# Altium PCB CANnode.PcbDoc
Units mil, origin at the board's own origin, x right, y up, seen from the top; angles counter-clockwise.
Board outline 2780 x 2140 mil, 4 copper layers (Top Layer, GND, 3V3, Bottom Layer), stack 53.911 mil thick; 99 components, 91 nets, 421 pads, 118 vias.
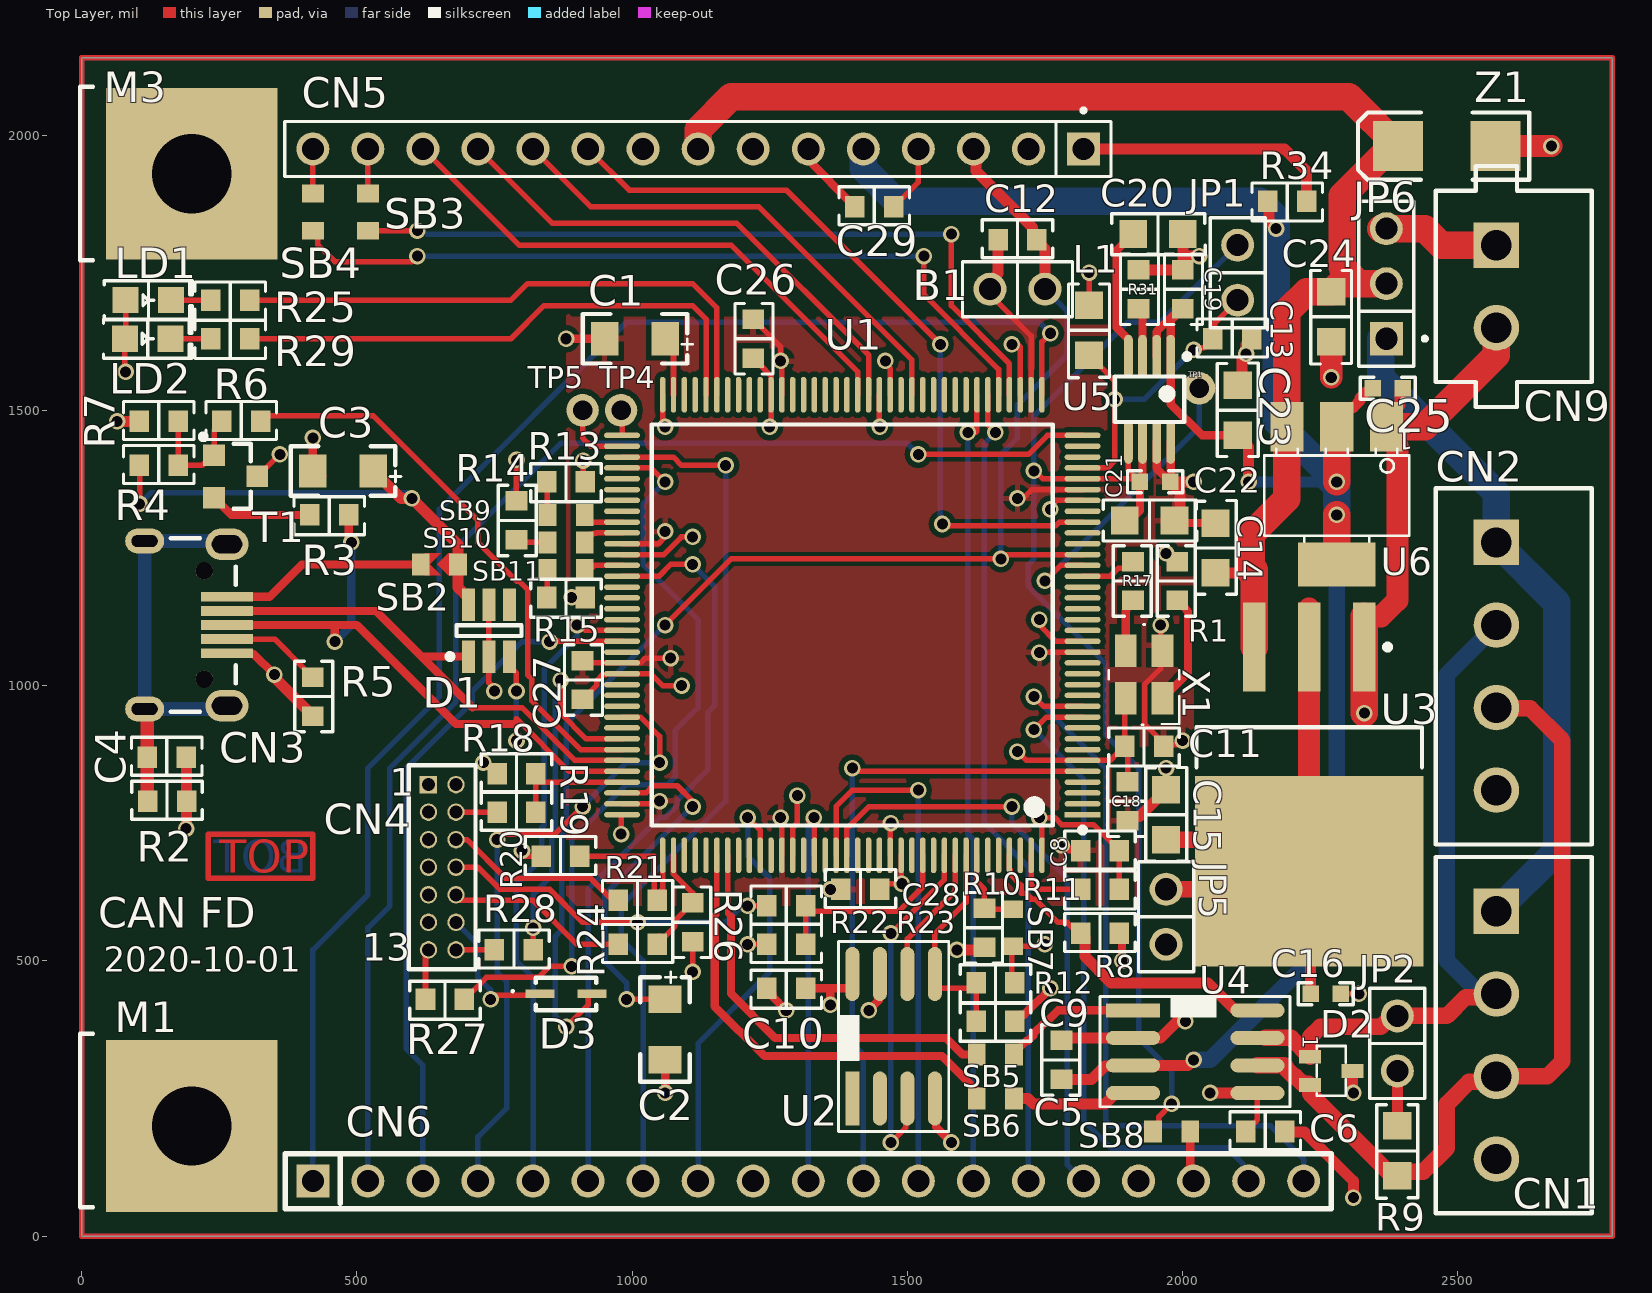
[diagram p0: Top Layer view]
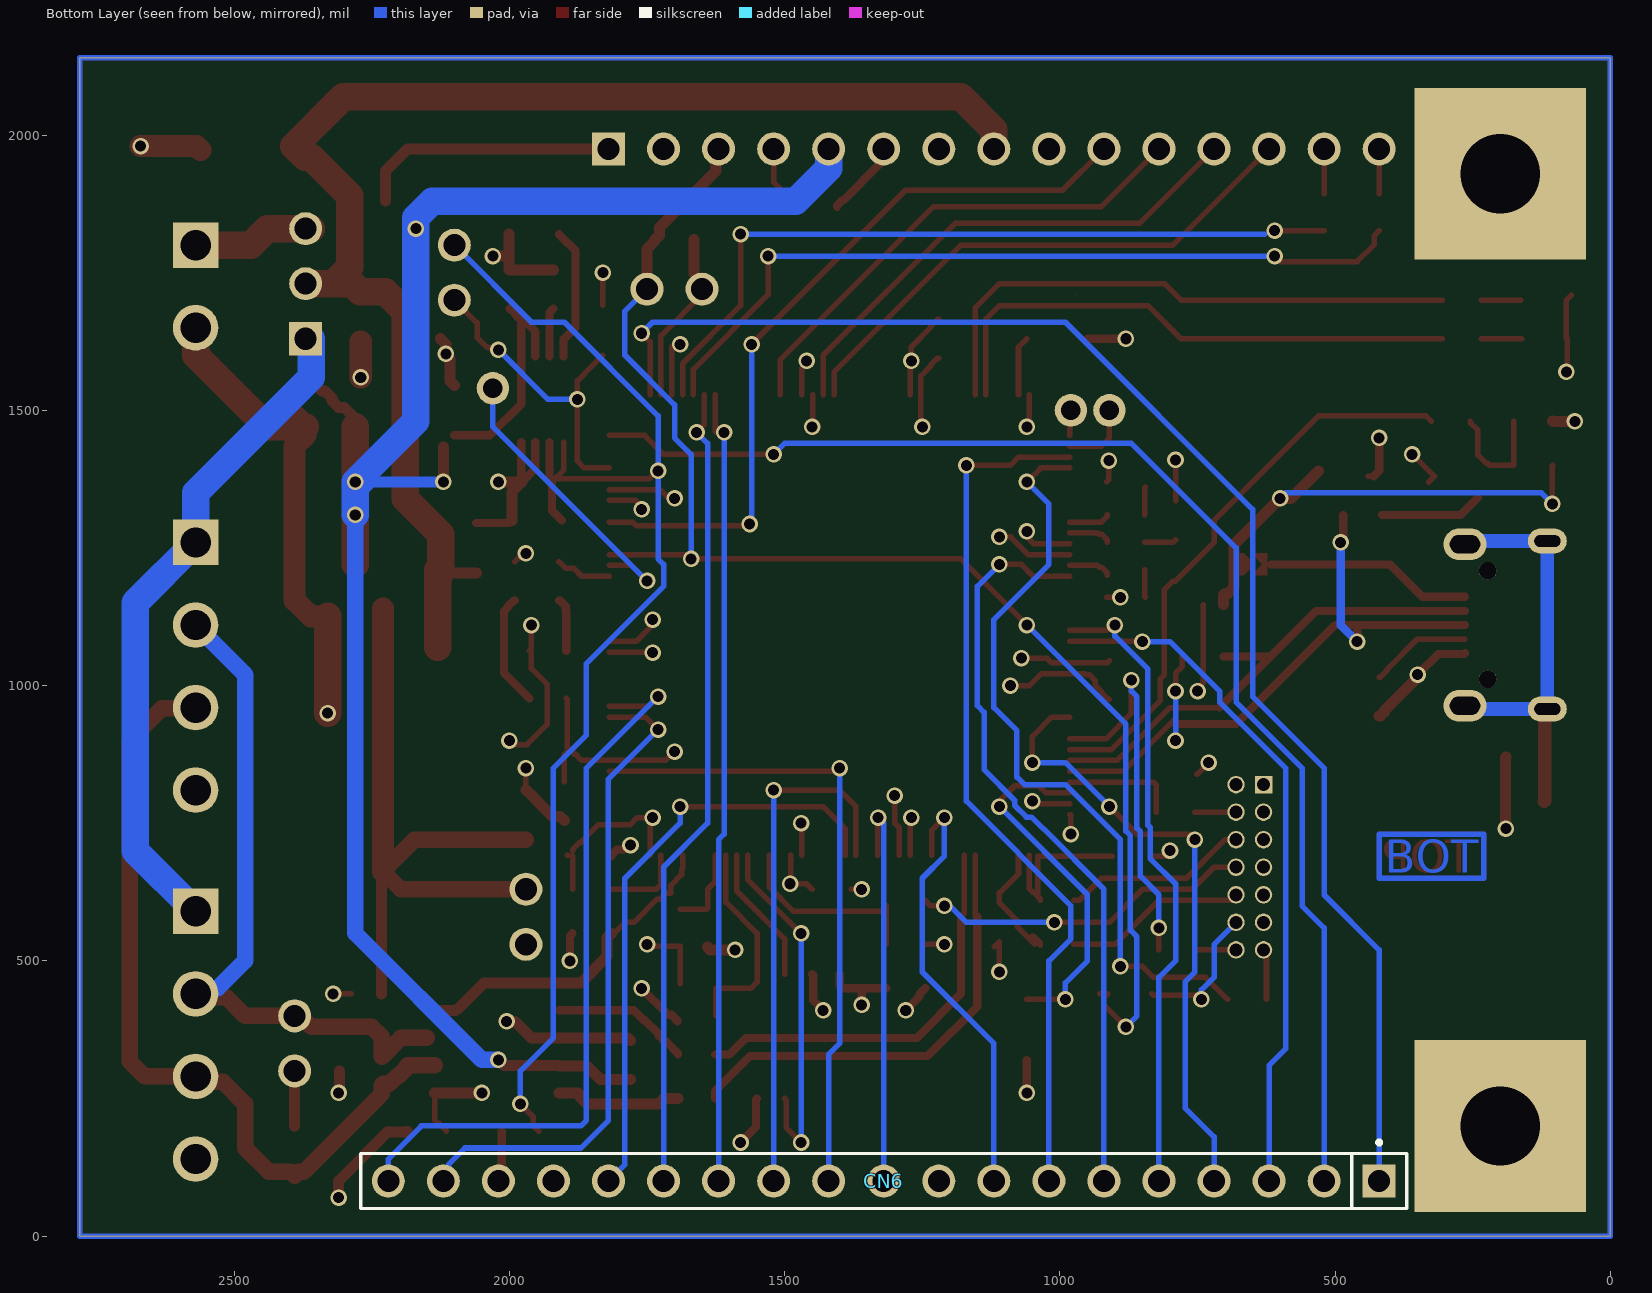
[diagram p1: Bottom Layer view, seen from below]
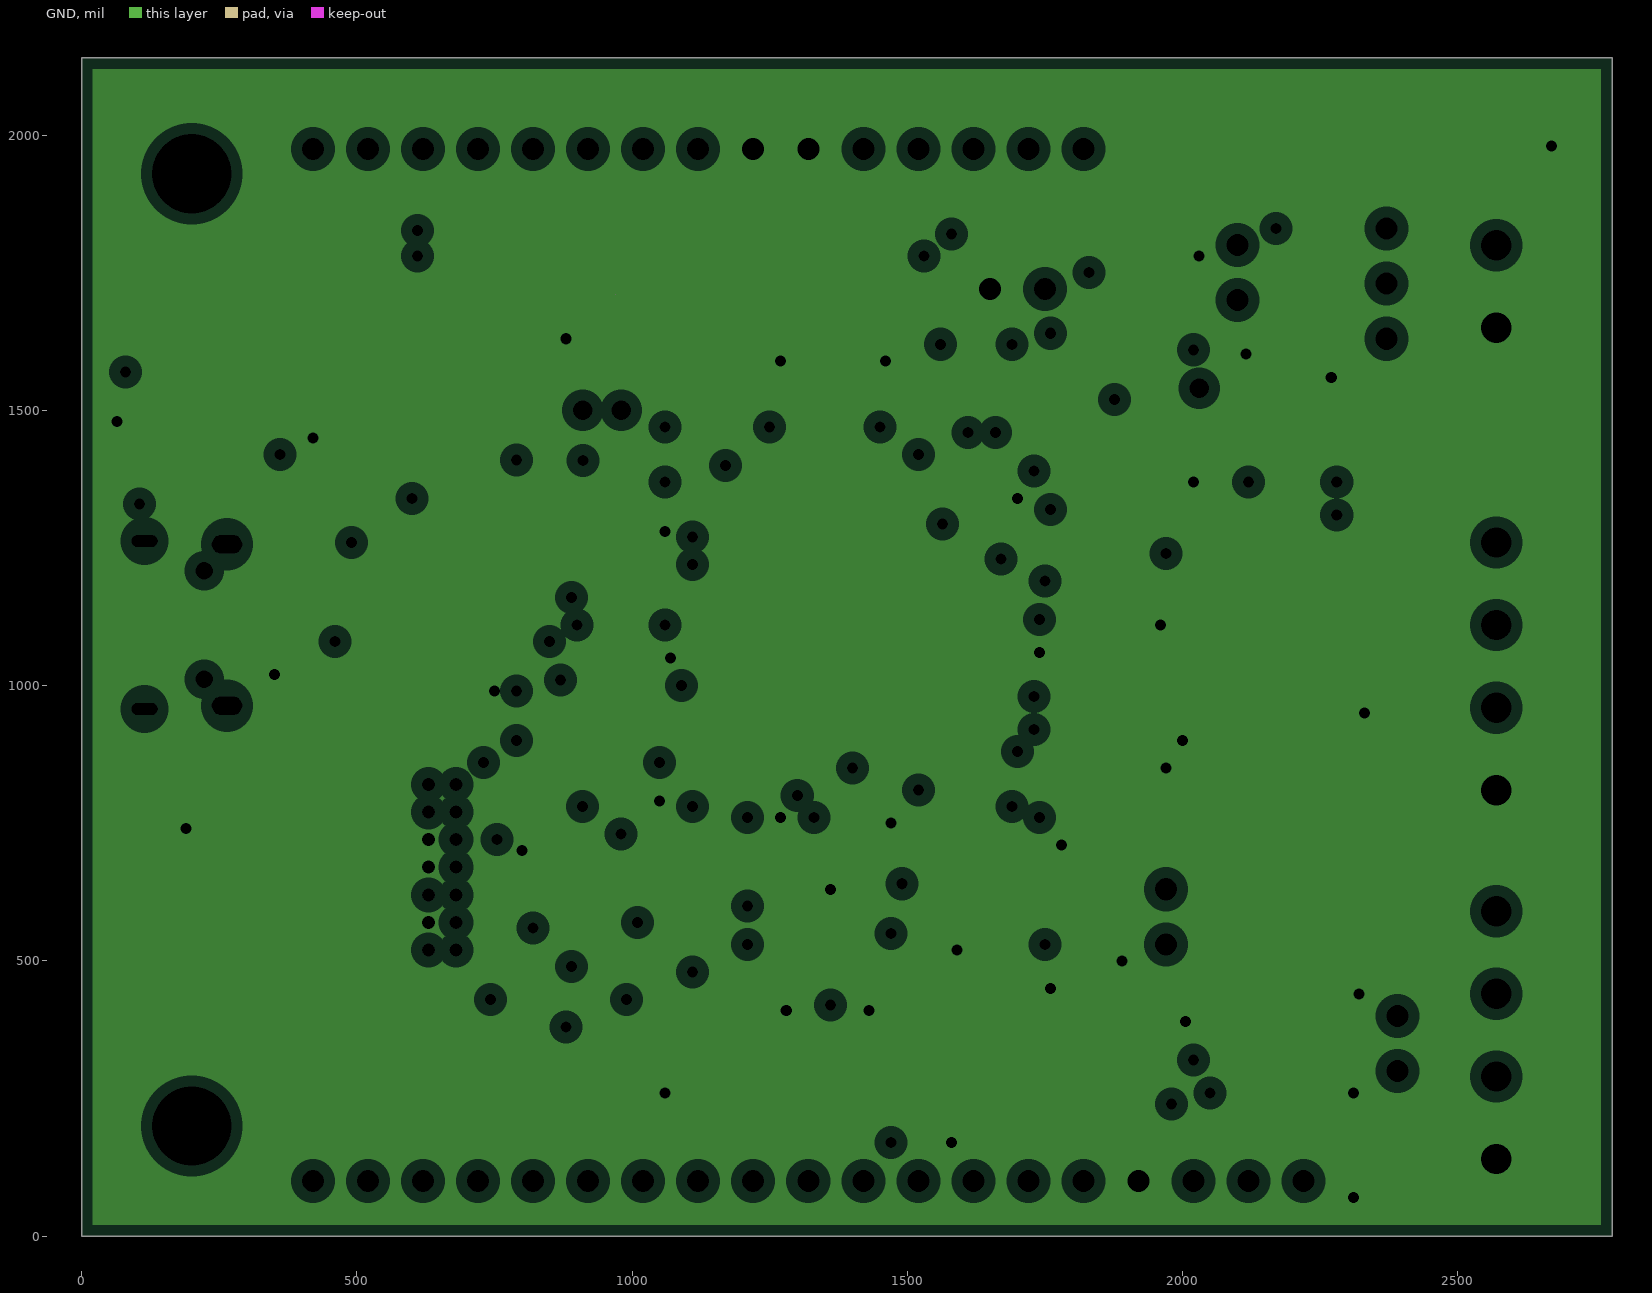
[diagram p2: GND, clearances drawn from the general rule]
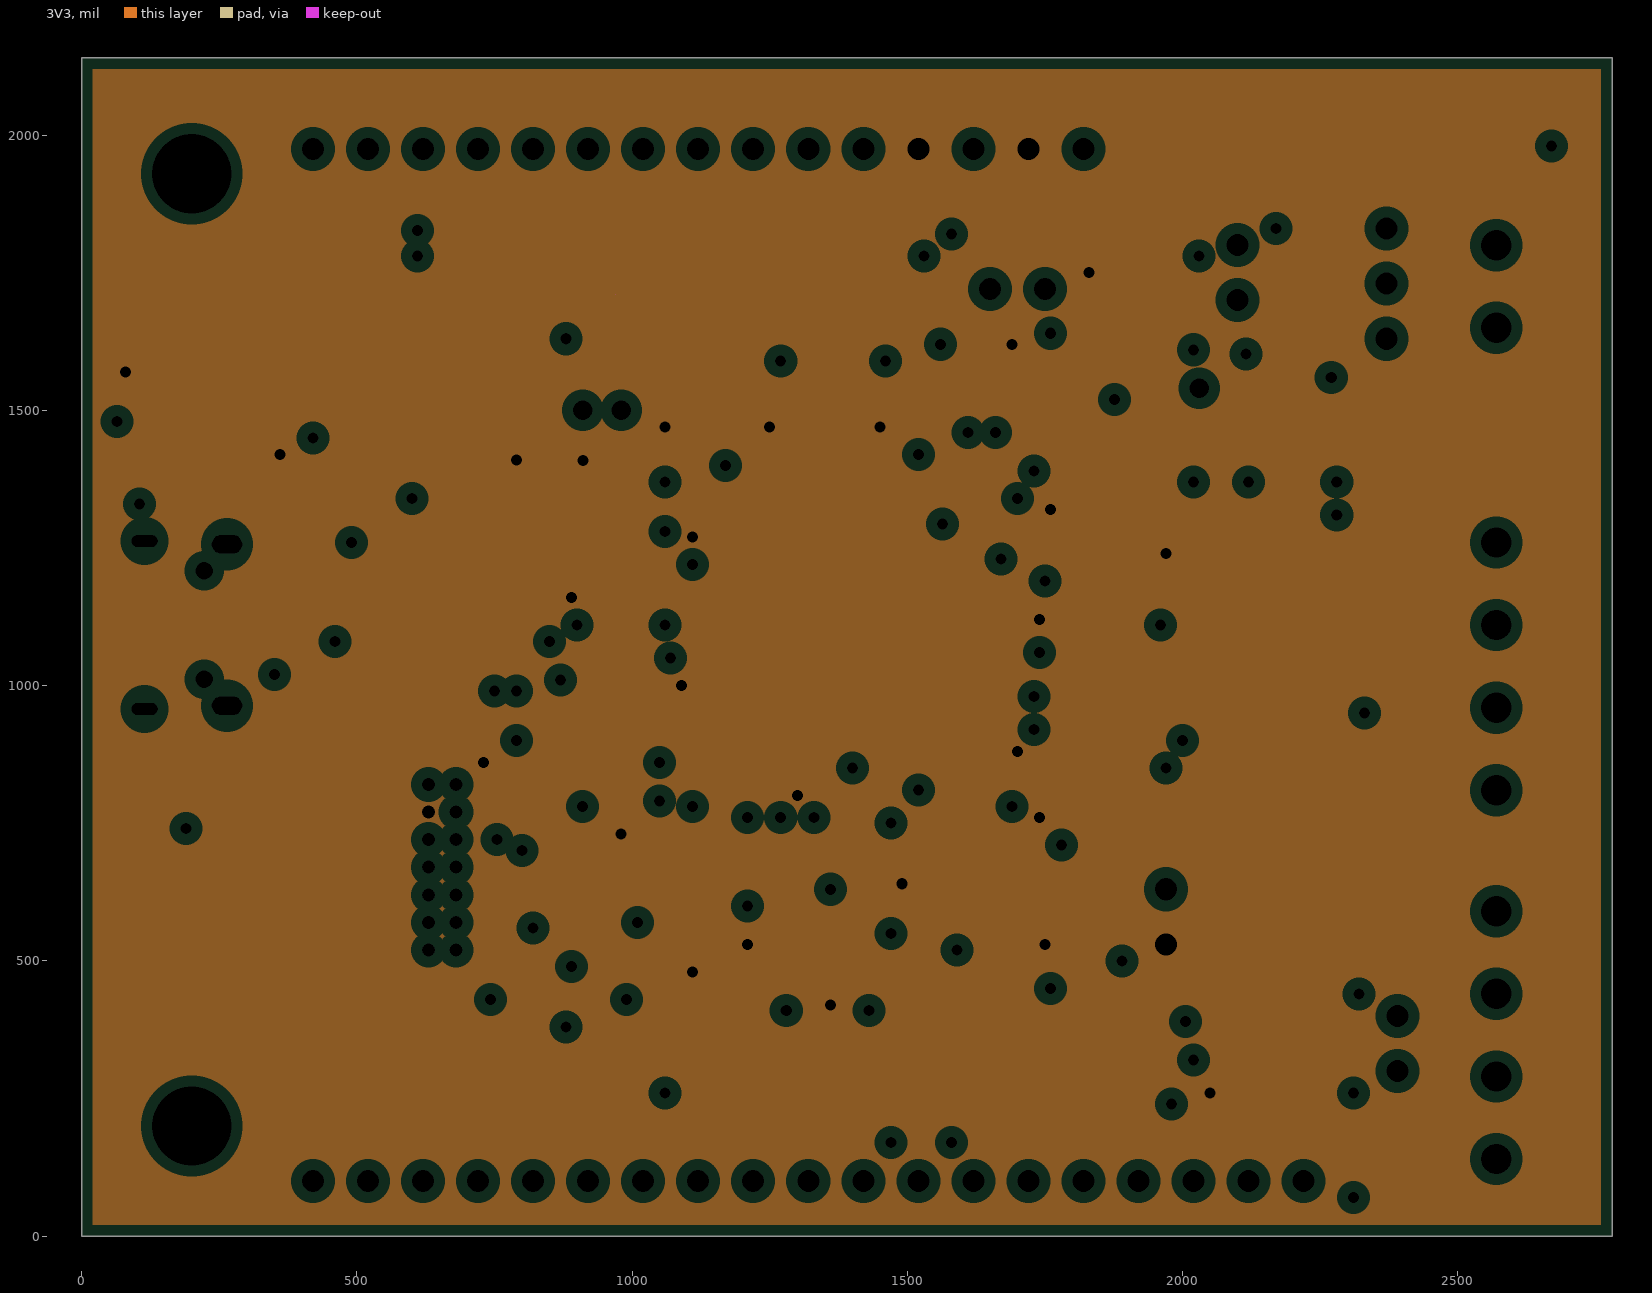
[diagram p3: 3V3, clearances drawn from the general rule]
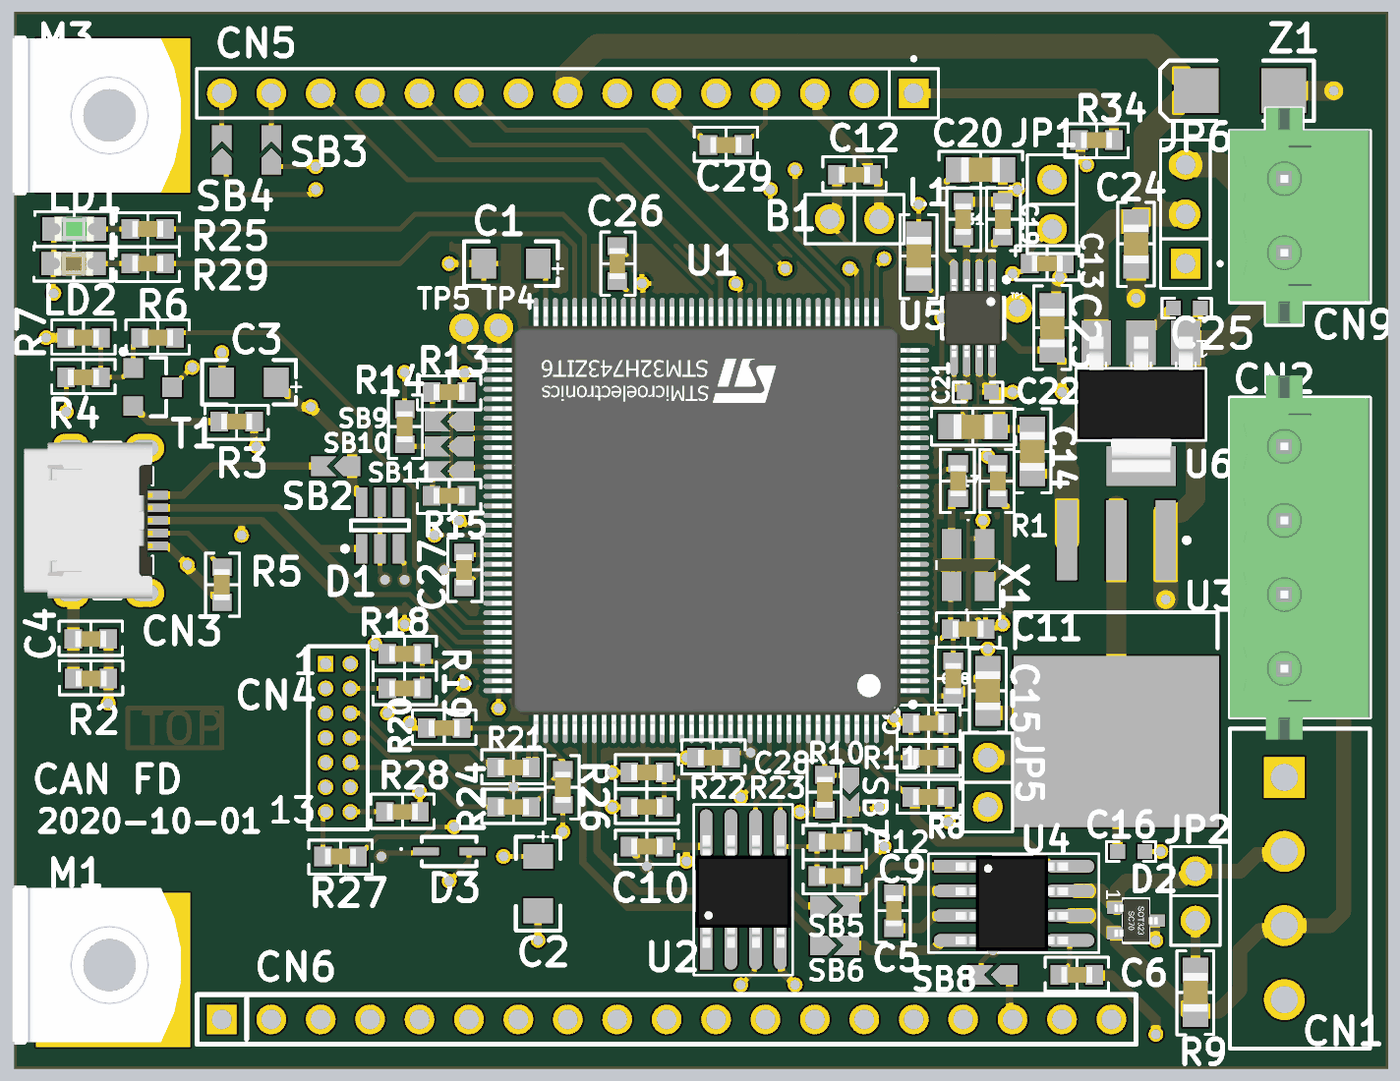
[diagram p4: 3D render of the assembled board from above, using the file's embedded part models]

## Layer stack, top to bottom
Top Solder: solder mask 1, SM-001, Dk 4
Top Layer: signal copper 1.3778
Dielectric 1: prepreg 5.1, PP-017, Dk 4.3
Dielectric 2: prepreg 5.1, PP-017, Dk 4.3
GND: plane copper 1.3778, net GND
Dielectric 3: core 28, Core-039, Dk 4.8
3V3: plane copper 1.3778, net 3V3
Dielectric 4: prepreg 5.1, PP-017, Dk 4.3
Dielectric 5: prepreg 5.1, PP-017, Dk 4.3
Bottom Layer: signal copper 1.3778
Bottom Solder: solder mask 1, SM-001, Dk 4

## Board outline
2780,0 2780,2140 0,2140 0,0
cut-out: 970,1710

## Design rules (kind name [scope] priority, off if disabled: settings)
Clearance [All] p1: gap=10 ignorepadtopadclearanceinfootprint=FALSE except(0: SMDPad-Region; 7: SMDPad-SMDPad; 8: Track-Track Track-SMDPad Track-THPad Track-Via Track-Fill Track-Poly Track-Region Track-Text Track-Hole SMDPad-THPad THPad-THPad Region-Region Region-Text Region-Hole)
ComponentClearance [All] p1: gap=0 collisioncheckmode=3 verticalgap=0 showdistances=FALSE
HoleSize [All] p1: absolutevalues=TRUE maxlimit=150 minlimit=15 maxpercent=80.000 minpercent=20.000
MinimumSolderMaskSliver [All] p1: minsoldermaskwidth=4
PlaneClearance [All] p1: clearance=20
PlaneConnect PlanePwr [InNetClass('3V3')] p1: pad.planeconnectstyle=Relief pad.reliefexpansion=10 pad.reliefentries=4 pad.reliefconductorwidth=15 pad.reliefairgap=15 via.planeconnectstyle=Direct via.reliefexpansion=10 via.reliefentries=4 via.reliefconductorwidth=10 via.reliefairgap=15
PlaneConnect PlaneGND [InNetClass('GND')] p2: pad.planeconnectstyle=Relief pad.reliefexpansion=10 pad.reliefentries=4 pad.reliefconductorwidth=15 pad.reliefairgap=15 via.planeconnectstyle=Direct via.reliefexpansion=20 via.reliefentries=4 via.reliefconductorwidth=15 via.reliefairgap=15
PolygonConnect [All] p1: connectstyle=Relief reliefconductorwidth=10 reliefentries=4 polygonreliefangle="90 Angle" airgapwidth=10
RoutingVias RoutingVias_1 [All] p1 off: holewidth=28 width=50 viastyle="Through Hole" minholewidth=28 minwidth=50 maxholewidth=28 maxwidth=50
RoutingVias [All] p2: holewidth=20 width=30 viastyle="Through Hole" minholewidth=20 minwidth=30 maxholewidth=20 maxwidth=30
SilkToSilkClearance [All] p1: silktosilkclearance=0
SilkToSolderMaskClearance [IsPad] p1: minsilkscreentomaskgap=0 clearancetoexposedcopper=TRUE
SolderMaskExpansion [All] p1: expansion=4
Width [All] p1: maxlimit=50 minlimit=10 preferedwidth=15 minimp=50.000000 maximp=50.000000 favimp=50.000000
23 further rules are at their usual default settings.

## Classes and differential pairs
net class 3V3: 3V3
net class GND: GND
component class U_Arduino: CN5 CN6 R34 SB3 SB4 SB8
component class U_PWR: C1 C2 C13 C14 C15 C16 C18 C19 C20 C21 C22 C23 C24 C25 CN9 JP1 JP5 JP6 L1 R31 U1 U3 U5 U6 Z1
component class U_MCU: B1 C8 C9 C10 C11 C12 C26 C27 C28 C29 CN4 D3 LD1 LD2 R1 R10 R11 R12 R13 R14 R15 R17 R18 R19 R20 R21 R22 R23 R24 R25 R26 R27 R28 R29 SB5 SB6 SB7 SB9 SB10 SB11 TP1 TP4 TP5 U2 X1
component class U_CANUSB: C3 C4 C5 C6 CN1 CN2 CN3 D1 D2 JP2 R2 R3 R4 R5 R6 R7 R8 R9 SB2 T1 U4
component class TopView: M1 M3

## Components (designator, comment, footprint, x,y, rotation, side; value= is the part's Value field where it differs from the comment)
B1 "" SIP2/2.54 1650,1720 r0 top
C1 "2.2uF" TAN-A 1060,1630 r0 top
C2 "2.2uF" TAN-A 1060,430 r90 top
C3 "4.7uF" TAN-A 530,1390 r0 top value=4.7µF
C4 "100nF" 0603#1 154.7,870 r0 top
C5 "100nF" 0603#1 1780,320 r90 top
C6 "100nF" 0603#1 2150,190 r0 top
C8 "Capacitor" 0603#1 1850,700 r0 top value=100nF
C9 "Capacitor" 0603#1 1660,390 r180 top value=30pF
C10 "Capacitor" 0603#1 1280,450 r180 top value=100nF
C11 "Capacitor" 0603#1 1930,890 r180 top value=100nF
C12 "100nF" 0603#1 1700,1810 r0 top value=100pF
C13 "Capacitor" 0603#1 2090,1630 r0 top value=100nF
C14 "10uF/25V" 0805 2060,1250 r90 top value=10uF
C15 "10uF/25V" 0805 1970,765.28 r90 top value=10uF
C16 "100nF" 0603C 2260,440 r180 top value=10nF
C18 "Capacitor" 0603#1 1900,790 r90 top value=100nF
C19 "100nF" 0603#1 2000,1720 r270 top value=10nF
C20 "1uF" 0805 1955.28,1820 r0 top
C21 "47uF" 0805 1940,1300 r0 top value=1uF
C22 "100nF" 0603C 1950,1370 r180 top value=10nF
C23 "10uF/25V" 0805 2100,1500 r90 top value=10uF
C24 "10uF/25V" 0805 2270,1670 r270 top value=10uF
C25 "100nF" 0603C 2372.5,1540 r180 top value=10nF
C26 "Capacitor" 0603#1 1220,1630 r270 top value=100nF
C27 "Capacitor" 0603#1 910,1010 r270 top value=100nF
C28 "Capacitor" 0603#2 1414.7,630 r0 top value=100nF
C29 "Capacitor" 0603#1 1440,1870 r0 top value=100nF
CN1 "MC000130" 691305330004 2601.5,365 r270 top
CN2 "MC000130" 691305330004 2601.5,1035 r270 top
CN3 "629105150521" USB_micro_629105150521 150,1110 r270 top
CN4 "STLINK_V3SET" HDR2X7--50mil 630,820 r270 top
CN5 "SSW-115-01-T-S" SIP15 1820,1974.8 r180 top
CN6 "SSW-119-01-T-S" sip19 420,100 r0 bottom
CN9 "691321300002" 691305330002 2601.5,1725 r270 top
D1 "ESDA6V1BC6" SOT23-6-L 740,1100 r90 top
D2 "ESDCAN02-2BWY" DIO_SOT323 2270,300 r270 top
D3 "BAT60JFILM" SOD-323 880,440 r180 top
JP1 "" SIP2/2.54 2100,1800 r270 top
JP2 "" SIP2/2.54 2390,400 r270 top
JP5 "" SIP2/2.54 1970,530 r90 top
JP6 "" SIP3 2370,1630 r90 top
L1 "BEAD" 0805 1830,1645.28 r270 top value=0.27@250MHz
LD1 "LED_green" "LED 0805/2012 GREEN" 121.34,1700 r0 top value=Green,KP-2012LSGC
LD2 "LED_red" "LED 0805/2012 RED" 120,1630 r0 top value=Red,KPT-2012EC
M1 "" "Keystone 614"#1 190,210 r0 top
M3 "" "Keystone 614"#2 190,1930 r0 top
R1 "Resistor" 0603#1 1990,1190 r90 top value=4K7
R2 "330" 0603#1 155.3,790 r0 top
R3 "1K5" 0603#1 450,1310 r180 top
R4 "10K" 0603#1 140,1400 r0 top
R5 "100K" 0603#1 420,980 r270 top
R6 "100" 0603#1 290,1480 r0 top
R7 "36K" 0603#1 140,1480 r0 top
R8 "10K" 0603#1 1850,550 r0 top
R9 "120" 0805 2390,154.72 r270 top
R10 "Resistor" 0603#1 1640,560 r90 top value=100K
R11 "Resistor" 0603#1 1850,630 r180 top value=10K
R12 "Resistor" 0603#1 1660,460 r180 top value=4K7
R13 "Resistor" 0603#1 880,1370 r180 top value=100K
R14 "Resistor" 0603#1 790,1300 r270 top value=100K
R15 "Resistor" 0603#3 880,1160 r180 top value=100K
R17 "Resistor" 0603#1 1910,1190 r90 top value=51R
R18 "Resistor" 0603#1 790,840 r0 top value=10K
R19 "22" 0603#1 790,770 r0 top
R20 "Resistor" 0603#1 870,690 r0 top value=10K
R21 "22" 0603#3 1010,610 r0 top
R22 "22" 0603#1 1280,600 r0 top
R23 "Resistor" 0603#1 1280,530 r0 top value=10K
R24 "22" 0603#3 1010,530 r0 top
R25 "Resistor" 0603#1 270,1700 r180 top value=1K
R26 "Resistor" 0603#1 1110,570 r90 top value=10K
R27 "22" 0603#1 660,430 r180 top
R28 "22" 0603#1 785.3,520 r0 top
R29 "Resistor" 0603#1 270,1630 r180 top value=1K
R31 "120K" 0603#1 1920,1720 r270 top
R34 "Resistor" 0603#1 2190,1880 r180 top value=1K
SB2 "Open" SB0603#1 650,1220 r0 top
SB3 "SB_ON" SB0603#2 520,1860 r270 top
SB4 "SB_ON" SB0603#2 420,1860 r270 top
SB5 "SB_ON" SB0603#2 1660,330 r180 top
SB6 "SB_ON" SB0603#2 1660,250 r180 top
SB7 "SB_ON" SB0603#3 1690,560 r90 top
SB8 "SB_OFF" SB0603#2 1980,190 r0 top
SB9 "SB_OFF" SB0603#3 880,1310 r0 top
SB10 "SB_OFF" SB0603#3 880,1260 r0 top
SB11 "SB_OFF" SB0603#3 880,1210 r0 top
T1 "BC847A" SOT-23 280,1380 r270 top
TP1 "OSCO" "Through Hole Pad"#1 1840,1520 r0 top
TP4 "CANRX" "Through Hole Pad"#2 980,1500 r90 top
TP5 "CANTX" "Through Hole Pad"#2 910,1500 r90 top
U1 "STM32H743ZIT6" FP-LQFP144-1A-IPC_B 1400,1110 r180 top
U2 "M24M02-DRMN6TP" SOIC-8 1400,250 r90 top
U3 "LD1086D2M33TR" D2PAK_A_M 2230,820 r270 top
U4 "MCP2562FD-E/SN" SOIC-8 1910,410 r0 top value=MCP2562FD
U5 "" SSOP8 1940,1520 r270 top value=REF6225IDGKT
U6 "LD1117S50TR" sot223 2280,1345 r180 top
X1 "Oscillator_4pins" OSC_NDK 1930,1020 r90 top value=25MHz
Z1 "SMAJ12A-TR" SMB 2480,1980 r180 top

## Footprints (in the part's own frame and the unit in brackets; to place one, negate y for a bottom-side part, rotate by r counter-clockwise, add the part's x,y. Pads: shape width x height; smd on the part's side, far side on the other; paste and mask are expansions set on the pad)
0603#1 [mm] "SMD 0603 Top"
  rect 0.9x1 smd: 1(-0.897,0) 2(0.897,0)
  silkscreen extent -1.63,-0.84 1.63,0.91, body extent -0.8,-0.41 0.8,0.41, height 0.82
0603#2 [mm] "SMD 0603 Top"
  rect 0.9x1 smd: 1(-0.897,0)
  rect 0.9x1 smd mask+0.051: 2(0.897,0)
  silkscreen extent -1.63,-0.84 1.63,0.91, body extent -0.8,-0.41 0.8,0.41, height 0.82
0603#3 [mm] "SMD 0603 Top"
  rect 0.9x1 smd mask+0.051: 1(-0.897,0) 2(0.897,0)
  silkscreen extent -1.63,-0.84 1.63,0.91, body extent -0.8,-0.41 0.8,0.41, height 0.82
0603C [mil]
  rect 30x30 smd: 1(27.5,0) 2(-27.5,0)
  silkscreen extent -50,-20 50,20
0805 [mm] "SMD 0805, Top"
  rect 1.27x1.3 smd: 1(-1.15,0) 2(1.15,0)
  silkscreen extent -2.13,-0.95 2.18,0.94, body extent -1,-0.64 1,0.64, height 1.26
691305330002 [mm] "Vertical PCB Header with Plastic Latch, pitch 3.81mm, 02p"
  rect 2.1x2.1 hole 1.4: 1(-1.905,-0.8)
  round 2.1 hole 1.4: 2(1.905,-0.8)
  silkscreen extent -5.56,-3.6 5.56,3.6, body extent -5.6,-3.6 5.51,3.6, height 9.25
691305330004 [mm] "Vertical PCB Header with Plastic Latch, pitch 3.81mm, 04p"
  rect 2.1x2.1 hole 1.4: 1(-5.715,-0.8)
  round 2.1 hole 1.4: 2(-1.905,-0.8) 3(1.905,-0.8) 4(5.715,-0.8)
  silkscreen extent -8.22,-3.6 8.22,3.6, body extent -2.54,-2.54 2.54,2.54, height 0.25
D2PAK_A_M [mm] "D2-PAK, 4-Leads, Body 9.2x10.2mm, Pitch 2.54mm, Lead Span 15.4mm, IPC Low Density"
  rect 4.1x1.05 smd: 1(-6.35,2.54) 2(-6.35,0) 3(-6.35,-2.54)
  rect 8.8x10.55 smd: 4(4,0)
  silkscreen extent -6.47,-5.2 -0.8,5.2, body extent -2.65,-5.2 6.7,5.2, height 4.6
DIO_SOT323 [mm]
  rect 0.635x1.016 smd mask+0.05: 1(-0.65,-0.975) 2(0.65,-0.975) 3(0,0.975)
  silkscreen extent -1.15,-0.67 1.15,0.67, body extent -1.15,-1.12 1.15,1.12, height 1.1
FP-LQFP144-1A-IPC_B [mm]
  rect 1.655x0.252 smd paste+0 mask+0: 1(-10.625,8.75)
  rrect100% 1.655x0.252 smd paste+0 mask+0: 2(-10.625,8.25) 3(-10.625,7.75) 4(-10.625,7.25) 5(-10.625,6.75) 6(-10.625,6.25) 7(-10.625,5.75) 8(-10.625,5.25) 9(-10.625,4.75) 10(-10.625,4.25) 11(-10.625,3.75) 12(-10.625,3.25) 13(-10.625,2.75) 14(-10.625,2.25) 15(-10.625,1.75) 16(-10.625,1.25) 17(-10.625,0.75) 18(-10.625,0.25) 19(-10.625,-0.25) 20(-10.625,-0.75) 21(-10.625,-1.25) 22(-10.625,-1.75) 23(-10.625,-2.25) 24(-10.625,-2.75) 25(-10.625,-3.25) 26(-10.625,-3.75) 27(-10.625,-4.25) 28(-10.625,-4.75) 29(-10.625,-5.25) 30(-10.625,-5.75) 31(-10.625,-6.25) 32(-10.625,-6.75) 33(-10.625,-7.25) 34(-10.625,-7.75) 35(-10.625,-8.25) 36(-10.625,-8.75) 73(10.625,-8.75) 74(10.625,-8.25) 75(10.625,-7.75) 76(10.625,-7.25) 77(10.625,-6.75) 78(10.625,-6.25) 79(10.625,-5.75) 80(10.625,-5.25) 81(10.625,-4.75) 82(10.625,-4.25) 83(10.625,-3.75) 84(10.625,-3.25) 85(10.625,-2.75) 86(10.625,-2.25) 87(10.625,-1.75) 88(10.625,-1.25) 89(10.625,-0.75) 90(10.625,-0.25) 91(10.625,0.25) 92(10.625,0.75) 93(10.625,1.25) 94(10.625,1.75) 95(10.625,2.25) 96(10.625,2.75) 97(10.625,3.25) 98(10.625,3.75) 99(10.625,4.25) 100(10.625,4.75) 101(10.625,5.25) 102(10.625,5.75) 103(10.625,6.25) 104(10.625,6.75) 105(10.625,7.25) 106(10.625,7.75) 107(10.625,8.25) 108(10.625,8.75)
  rrect100% 0.252x1.655 smd paste+0 mask+0: 37(-8.75,-10.625) 38(-8.25,-10.625) 39(-7.75,-10.625) 40(-7.25,-10.625) 41(-6.75,-10.625) 42(-6.25,-10.625) 43(-5.75,-10.625) 44(-5.25,-10.625) 45(-4.75,-10.625) 46(-4.25,-10.625) 47(-3.75,-10.625) 48(-3.25,-10.625) 49(-2.75,-10.625) 50(-2.25,-10.625) 51(-1.75,-10.625) 52(-1.25,-10.625) 53(-0.75,-10.625) 54(-0.25,-10.625) 55(0.25,-10.625) 56(0.75,-10.625) 57(1.25,-10.625) 58(1.75,-10.625) 59(2.25,-10.625) 60(2.75,-10.625) 61(3.25,-10.625) 62(3.75,-10.625) 63(4.25,-10.625) 64(4.75,-10.625) 65(5.25,-10.625) 66(5.75,-10.625) 67(6.25,-10.625) 68(6.75,-10.625) 69(7.25,-10.625) 70(7.75,-10.625) 71(8.25,-10.625) 72(8.75,-10.625) 109(8.75,10.625) 110(8.25,10.625) 111(7.75,10.625) 112(7.25,10.625) 113(6.75,10.625) 114(6.25,10.625) 115(5.75,10.625) 116(5.25,10.625) 117(4.75,10.625) 118(4.25,10.625) 119(3.75,10.625) 120(3.25,10.625) 121(2.75,10.625) 122(2.25,10.625) 123(1.75,10.625) 124(1.25,10.625) 125(0.75,10.625) 126(0.25,10.625) 127(-0.25,10.625) 128(-0.75,10.625) 129(-1.25,10.625) 130(-1.75,10.625) 131(-2.25,10.625) 132(-2.75,10.625) 133(-3.25,10.625) 134(-3.75,10.625) 135(-4.25,10.625) 136(-4.75,10.625) 137(-5.25,10.625) 138(-5.75,10.625) 139(-6.25,10.625) 140(-6.75,10.625) 141(-7.25,10.625) 142(-7.75,10.625) 143(-8.25,10.625) 144(-8.75,10.625)
  silkscreen extent -10.75,-9.25 9.25,9.58, body extent -11.7,-11.7 11.7,11.7, height 0.25
HDR2X7--50mil [mm] "Connector; Header; 7x2 Position, 50mil"
  rect 0.8x0.8 hole 0.6: 1(0,0)
  round 0.8 hole 0.6: 2(0,1.27) 3(1.27,0) 4(1.27,1.27) 5(2.54,0) 6(2.54,1.27) 7(3.81,0) 8(3.81,1.27) 9(5.08,0) 10(5.08,1.27) 11(6.35,0) 12(6.35,1.27) 13(7.62,0) 14(7.62,1.27)
  silkscreen extent -0.9,-0.9 8.52,2.17
"Keystone 614"#1 [mm]
  rect 7.92x7.92 hole 3.66: 1(0.254,-0.254)
  silkscreen extent -4.9,-4 -4.3,4, body extent -4.93,-3.96 3.77,3.96, height 10.66
"Keystone 614"#2 [mm]
  rect 7.92x7.92 hole 3.66: 1(0.254,0)
  silkscreen extent -4.9,-4 -4.3,4, body extent -4.93,-3.96 3.77,3.96, height 10.66
"LED 0805/2012 GREEN" [mm] "Chip Diode, 2-Leads, Body 2.00x1.25mm, IPC Medium Density"
  rect 1.2x1.2 smd: 1(-1.05,0) 2(1.05,0)
  silkscreen extent -2.03,-0.9 2.03,0.9, body extent -1,-0.62 1,0.63, height 0.9
"LED 0805/2012 RED" [mm] "Chip Diode, 2-Leads, Body 2.00x1.25mm, IPC Medium Density"
  rect 1.2x1.2 smd: 1(-1.05,0) 2(1.05,0)
  silkscreen extent -2.03,-0.9 2.03,0.9, body extent -1,-0.62 1,0.63, height 0.9
OSC_NDK [mm]
  rect 1.5x1 smd mask+0.05: 1(-1.1,-0.85) 2(1.1,-0.85) 3(1.1,0.85) 4(-1.1,0.85)
  silkscreen extent -2.31,-1.63 2.31,1.63, body extent -1.3,-1.05 1.3,1.05, height 0.91
SB0603#1 [mil] "Jumper"
  rect 32x40 smd: 1(33.75,0) 2(-33.75,0)
  Top Layer region: -26.25,0 -18,0 2,-20 -26.25,-20
  Top Layer region: -26.25,0 -18,0 2,20 -26.25,20
  Top Layer region: 23.75,20 16,20 -4,0 16,-20 23.75,-20
SB0603#2 [mil] "Jumper"
  rect 32x40 smd: 1(33.75,0) 2(-33.75,0)
SB0603#3 [mil] "Jumper"
  rect 32x40 smd mask+2: 1(33.75,0) 2(-33.75,0)
SIP2/2.54 [mil]
  round 60 hole 40: 1(0,0) 2(100,0)
  silkscreen extent -50,-50 150,50
SIP3 [mil]
  rect 60x60 hole 40: 1(0,0)
  round 60 hole 40: 2(100,0) 3(200,0)
  silkscreen extent -50,-72 250,50
SIP15 [mil]
  rect 60x60 hole 40: 1(0,0)
  round 60 hole 40: 2(100,0) 3(200,0) 4(300,0) 5(400,0) 6(500,0) 7(600,0) 8(700,0) 9(800,0) 10(900,0) 11(1000,0) 12(1100,0) 13(1200,0) 14(1300,0) 15(1400,0)
  silkscreen extent -50,-72 1451,50
sip19 [mil]
  rect 60x60 hole 40: 1(0,0)
  round 60 hole 40: 2(100,0) 3(200,0) 4(300,0) 5(400,0) 6(500,0) 7(600,0) 8(700,0) 9(800,0) 10(900,0) 11(1000,0) 12(1100,0) 13(1200,0) 14(1300,0) 15(1400,0) 16(1500,0) 17(1600,0) 18(1700,0) 19(1800,0)
  silkscreen extent -50,-72 1850,50
SMB [mm] "DO-214-AA/SMB; 2 C-Bend Leads; Body 5.3 x 3.6 mm, inc. leads (LxW)"
  rect 2.3x2.3 smd: 1(-2.25,0) 2(2.25,0)
  silkscreen extent -3.8,-1.55 4.1,1.55
SOD-323 [mm] "Diode"
  rect 1.35x0.4 smd: 1(-1.2,0) 2(1.2,0)
  silkscreen extent -1.4,-0.75 2.51,0.75, body extent -1.35,-0.72 1.35,0.72, height 1.17
SOIC-8 [mm]
  rect 2.5x0.65 smd: 1(0,0)
  oval 2.5x0.65 smd: 2(0,-1.27) 3(0,-2.54) 4(0,-3.81) 5(5.74,-3.81) 6(5.74,-2.54) 7(5.74,-1.27) 8(5.74,0)
  silkscreen extent -1.52,-4.44 7.24,0.64, body extent -0.13,-4.36 5.65,0.55, height 1.45
SOT23-6-L [mm]
  rect 1.5x0.6 smd: 1(-1.2,0.95) 2(-1.2,0) 3(-1.2,-0.95) 4(1.2,-0.95) 5(1.2,0) 6(1.2,0.95)
  silkscreen extent -1.32,-1.5 0.25,1.92, body extent -0.86,-1.51 0.87,1.52, height 1.25
sot223 [mil]
  rect 60x90 smd mask+1.97: 1(-90.55,-125) 2(0,-125) 3(90.55,-125)
  rect 140x80 smd mask+1.97: 4(0,125)
  silkscreen extent -132,-85 132,84, body extent -132,-137 132,137, height 71
SOT-23 [mm]
  rect 1x1 smd: 1(-0.98,-1) 2(0.98,-1) 3(0,1)
  silkscreen extent -1.95,-1.62 1.5,0.7, body extent -1.52,-0.7 1.52,0.7, height 1.11
SSOP8 [mm] "SOP, 8-Leads, Body 2.9x3.2mm, Pitch 0.65mm, IPC Medium Density"
  oval 2x0.4 smd mask+0.051: 1(-1.975,0.975) 2(-1.975,0.325) 3(-1.975,-0.325) 4(-1.975,-0.975) 5(1.975,-0.975) 6(1.975,-0.325) 7(1.975,0.325) 8(1.975,0.975)
  silkscreen extent -2.1,-1.6 1.05,1.85, body extent -2.01,-1.47 2.01,1.48, height 1.3
TAN-A [mil]
  rect 50x60 smd: 1(0,0) 2(-110,0)
  silkscreen extent -150,-45 50,45
"Through Hole Pad"#1 [mm]
  round 1.5 hole 0.9: 1(4.826,0.508)
"Through Hole Pad"#2 [mm]
  round 1.5 hole 0.9 mask+0.051: 1(0,0)
USB_micro_629105150521 [mm] "Micro USB 2.0 SMT Type B Horizontal 5 Contacts High Current"
  rect 0.45x2.4 smd: 1(-1.3,2.9) 2(-0.65,2.9) 3(0,2.9) 4(0.65,2.9) 5(1.3,2.9)
  round 0.8 hole 0.8 unplated: MH1(-2.5,1.85) MH2(2.5,1.85)
  oval 1.15x1.8 hole 0.55 slot 1.2 at 90 deg: Shell(-3.875,-0.9) Shell(3.875,-0.9)
  oval 1.45x2 hole 0.85 slot 1.4 at 90 deg: Shell(-3.725,2.9) Shell(3.725,2.9)
  silkscreen extent -4,0.3 4,3.3, body extent -4,-3.3 4,3.3, height 2.75

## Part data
B1 JP1 JP5: library part JP2, "LED, error red. 2 PIN berg"
C1 C2: library part Cap_2.2uF_X7R_10%_0805, "Capacitor,2.2uF,16V, X7R,10%,0805,YAGEO", Manuf_1=YAGEO, Manuf_Part_1=CC1206KKX7R7BB225, Supplier Part Number 1=1457418
C3: library part "CAP SMD 0603  X5R 1µF 25V 10%", "4.7uF tantalium", Rated voltage=25V, Supplier Part Number 1=2852683, Temperature Max=+125°C, Temperature Min=-55°C, Tolerance=10%
C4 C5 C6: library part Cap, "Capacitor 0805", Supplier Part Number 1=2896561
C8 C10 C11 C13 C18 C26 C27 C28 C29: library part MCD-00102, "Capacitor, MLCC, 100nF, 16V, X7R, 10%, 0603 T=0,5mm", Manufacturer=WÜRTH, Manufacturer_Part_Number=885012206071, Package=C0603, Supplier Part Number 1=2495173
C9: library part MCD-00102, "Capacitor, MLCC, 30pF", Manufacturer=VISHAY, Manufacturer_Part_Number=VJ0603D300JXPAJ, Package=C0603, Supplier Part Number 1=2134029
C12: library part CAP, "Capacitor", Supplier Part Number 1=2896561
C14 C15 C23 C24: library part "Cap Pol1", "Polarized Capacitor (Radial)", Supplier Part Number 1=1735530
C16 C19 C22 C25: library part Cap, "Capacitor"
C20: library part Cap, "Capacitor, MCC, 0805, 10%", Manufacturer=WURTH, Manufacturer_Part_Number=885012207022, Supplier Part Number 1=2534053
C21: library part Cap, "Capacitor, MCC, 0805, 6.3V, 20%,X5R", Manufacturer=WURTH, Manufacturer_Part_Number=885012107006, Supplier Part Number 1=2495151
CN1 CN2: library part 691305340004, "Serie 3053 - 3.81mm Horizontal PCB Header with Plastic Latch WR-TBL, 4 pin", Operating Temperature="-40 to 105 degC", Supplier Part Number 1=2008110
CN3: "Micro USB 2.0 Type B Receptacle WR-COM, Horizontal, SMT, with Pegs, High Current at Pin 1 & Pin 5", Contact Resistance="30 mOhm", Operating Temperature="-40 to 85 degC", Rated Current="3 A", Supplier Part Number 1=2470822, Working Voltage="30 VAC"
CN4: "STLINK-V3SET -  Programmer / Debugger", Supplier Part Number 1=2356246
CN5: library part MHDR1X15, "Header, 15-Pin", Manufacturer=SAMTEC, Supplier Part Number 1=2779587
CN6: library part MHDR1X19, "Header, 19-Pin", Manufacturer=SAMTEC, Supplier Part Number 1=1804475
CN9: "Serie 321 - 3.81mm Vertical PCB Header WR-TBL, 2 pin", Supplier Part Number 1=1642012
D1: "4-line ESD protection", Manuf_1=STM, Manuf_Part_1=ESDA5V3L, Supplier Part Number 1=2353644
D2: "ESD Suppressor TVS ±30kV 3-Pin SOT-323 T/R", Manufacturer=STMicroelectronics
D3: library part Diode, "Default Diode", Supplier Part Number 1=1467544
JP2: library part JP2, "2 PIN berg"
JP6: library part Jumper3
L1: library part MCD-00047, "SMD Chip ferrite bead, 0.27R@250MHz +/-25%, 500mA, 0805", Manufacturer=COILCRAFT, Manufacturer_Part_Number=0805CS-330XJLB, Supplier Part Number 1=2286409
LD1: library part MCD-00050, "LED, Green, 0805", Manufacturer=KINGBRIGHT, Manufacturer_Part_Number=KP-2012LSGC, Supplier Part Number 1=2463991
LD2: library part MCD-00049, "LED, Red, 0603", Manufacturer=KINGBRIGHT, Manufacturer_Part_Number=KPT-2012EC, Supplier Part Number 1=2099236
M1 M3: library part TP, "TAVTARTO"
R1: library part MCD-00053, "Resistor,10K,0603,1%,1/16W", Manufacturer="TE CONNECTIVITY", Manufacturer_Part_Number=CRGCQ0603F4K7, Package=R0603, Supplier Part Number 1=2861469
R2: library part Resistor_ST, "Resistor 0805"
R3: library part Resistor_ST, "Resistor 0603"
R4 R7 R8: library part Res1, "Resistor"
R5: library part Resistor_ST, "Resistor  0805"
R6: library part Resistor_ST, "Resistor 0402 / 0603 / 0805"
R9: library part Resistor_ST, "Resistor  0805", Manufacturer="TE CONNECTIVITY", Manufacturer_Part_Number=CRGCQ0805F120R, Supplier Part Number 1=2861511
R10 R13 R14 R15: library part MCD-00053, "Resistor,100K,0603,5%,1/10W", Manufacturer="TE CONNECTIVITY", Manufacturer_Part_Number=CRGCQ0603J100K, Package=R0603
R11 R18 R20 R23 R26: library part MCD-00053, "Resistor,10K,0603,1%,1/16W", Manufacturer="TE CONNECTIVITY", Manufacturer_Part_Number=CRGCQ0603J10K, Package=R0603
R12: library part MCD-00053, "Resistor,10K,0603,1%,1/16W", Manufacturer="TE CONNECTIVITY", Manufacturer_Part_Number=CRGCQ0603J10K, Package=R0603, Supplier Part Number 1=2861870
R17: library part MCD-00485, "Resistor,51R,0603,1%,1/16W", Manufacturer=MULTICOMP, Manufacturer_Part_Number=MCWR06X51R0FTL, Package=R0603
R19 R21 R22 R24 R27 R28: library part Resistor_ST, "Resistor 0805", Manufacturer="TE CONNECTIVITY", Manufacturer_Part_Number=CRGCQ0603F22R, Supplier Part Number 1=2861441
R25 R34: library part MCD-00225, "Resistor,1K,0603,1%,1/10W", Manufacturer="TE CONNECTIVITY", Manufacturer_Part_Number=CRGH0603F1K0, Package=R0603, Supplier Part Number 1=2332003
R29: library part MCD-00507, "Resistor,1K,0402,1%,1/16W", Manufacturer="TE CONNECTIVITY", Manufacturer_Part_Number=CRGH0603F1K0, Package=R0603, Supplier Part Number 1=2332003
R31: library part MCD-00166, "Resistor,120K,0603,1%,1/16W", Manufacturer="TE CONNECTIVITY", Manufacturer_Part_Number=CRGCQ0805F120K, Package=R0805
SB2: library part "Circuit Breaker", "Circuit Breaker"
SB3 SB4 SB5 SB6 SB7: library part MCD-00071, "Solder Bridge ON"
SB8 SB9 SB10 SB11: library part MCD-00072, "Solder Bridge OFF"
T1: library part NPN, "NPN Bipolar Transistor", Supplier Part Number 1=1081231
TP1 TP4 TP5: library part TP
U1: library part CMP-12105-000003-1, "IC MCU 32BIT 2MB FLASH 144LQFP", Ambient Temperature Range High=+85°C, Ambient Temperature Range Low=-40°C, Frequency=400MHz, Manufacturer=STMicroelectronics, Max Junction Temp=+125°C, Max Supply Voltage=3.6V, Min Supply Voltage=1.62V, Package=LQFP144-1A, Supplier Part Number 1=2820778, Temperature="-40°C to +85°C"
U2: "2-Mbit serial I2C bus EEPROM", Supplier Part Number 1=2849970
U3: library part CMP-0244-00505-1, "1.5A, Low Drop Positive Voltage Regulator, 3.3V, 4-Pin D2PAK/A, Tape and Reel", Supplier Part Number 1=2112622
U4: library part MCP2562FD, "CAN Flexible Data Rate Transceiver", Manufacturer=MICROCHIP, Supplier Part Number 1=2434899
U5: library part MCD-01138, "IC VREF SERIES 2.5V 8VSSOP", Manufacturer=TI, Manufacturer_Part_Number=REF6225IDGKT, Package=VSSOP8, Supplier Part Number 1=2673366
U6: library part MCD-00088, "IC REG LDO 5V 0.8A SOT223", Manufacturer=STMICROELECTRONICS
X1: library part MCD-00597, "Oscillator 25.00Mhz, -+50PPM, 3.3V, Temp -55 to +125°C", Manufacturer=MULTICOMP, Manufacturer_Part_Number=MCSJK-3N-25.00-3.3-50-C
Z1: library part "D Schottky", "Schottky Diode", Supplier Part Number 1=9802754

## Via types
v1: diameter 30, hole 20, Top Layer to Bottom Layer, 118 vias

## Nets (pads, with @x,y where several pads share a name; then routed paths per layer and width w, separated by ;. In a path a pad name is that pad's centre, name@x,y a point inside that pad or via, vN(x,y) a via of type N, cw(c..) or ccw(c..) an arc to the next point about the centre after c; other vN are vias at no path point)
3V3: C6.1 C8.2 C10.1 C11.2 C18.2 C26.2 C27.2 C28.2 C29.2 CN4.3 CN5.2 CN5.4 JP5.1 L1.1 LD1.1 LD2.1 R1.2 R11.1 R12.1 R13.1 R14.1 R15.1 R18.1 R23.1 R26.1 SB7.2 T1.3 U1.6 U1.17 U1.30 U1.39 U1.52 U1.62 U1.72 U1.84 U1.95 U1.108 U1.121 U1.131 U1.144 U2.8 U4.5 X1.4 | length 2936.9
  Top Layer w10: LD1.1@71.34,1708.66 LD1.1 80,1631.34 LD2.1 78.66,1571.34 v1(80,1570) ; T1.3@330,1369.37 T1.3 359.37,1420 v1(360,1420) ; v1(730,860) R18.1@751.21,838.79 ; R14.1 v1(790,1410) ; v1(890,1160) R15.1 ; C27.2 911.97,974.7 924.69,987.42 924.69,989.39 936.09,1000.8 936.09,1009.18 946.62,1019.7 952.41,1019.7 954.12,1021.42 U1.95 1034.04,1021.42 1055.46,1000 v1(1090,1000) ; v1(911.17,1408.83) 911.17,1374.12 R13.1 ; v1(980,730) U1.108@980,765.48 ; U1.108@980.03,765.51 U1.108 ; U1.84 1057.55,1237.95 1089.6,1270 v1(1110,1270) ; U1.72 1055.51,1479.9 1060,1475.41 v1(1060,1470) ; v1(1110,480) R26.1 R26.1@1118.83,525.88 ; v1(1210,530) R23.1 ; C26.2 1221.97,1594.7 1234.69,1581.99 1234.69,1580.02 1252.36,1562.34 U1.62 1252.36,1472.36 v1(1250,1470) ; U1.121 1291.73,741.73 1300,750 v1(1300,800) ; U1.52 1449.21,1470.79 v1(1450,1470) ; C28.2 1460,640 1487.17,640 1488.58,641.42 U1.131 ; C29.2 1475.3,1871.97 1488.01,1884.69 1489.98,1884.69 1520,1914.7 CN5.4 ; R12.1@1690,458.01 SB7.2 1746.25,526.25 v1(1750,530) ; v1(1690,1620) 1700,1620 1705.12,1614.88 U1.39 ; v1(1700,880) 1716.06,863.94 U1.6 1868.64,863.94 1880.02,875.31 1881.99,875.31 C11.2@1888.35,881.67 ; v1(1740,760) 1767.9,760 1780.36,747.54 1837.75,747.54 1870.61,714.69 1872.58,714.69 1885.3,701.97 C8.2 ; v1(1740,1120) 1740,1110 1769.53,1080.47 U1.17 ; U1.144 v1@1744.49,755.51 ; v1(1760,1320) 1760,1325.64 1770.74,1336.38 U1.30 ; L1.1 v1(1830,1750) ; R11.1 1885.3,690 1887.19,690.37 C8.2@1895.3,691.97 ; X1.4 1894.7,974.86 C11.2 1894.7,888.03 C11.2@1888.35,881.67 ; C18.2 1900,875.31 1893.64,881.67 C11.2@1888.35,881.67 ; v1(1970,1240) 1970,1243.33 1975.31,1238.01 1977.28,1238.01 R1.2 ; C6.1 2114.7,191.97 2127.42,204.69 2129.39,204.69 2135.98,211.28 U4.5
  Top Layer w15: C10.1 1360,450 ; v1(1360,420) 1360,450 ; U2.8 1400,454.89 1395.11,450 1360,450
  Top Layer w20: v1(2050,260) U4.5
  other v1: 1490,640
ADAC1: SB3.1 U1.40 | length 1377.8
  Top Layer w10: SB3.1 v1(610,1826.25) ; v1(1580,1820) 1580,1690 1685.43,1584.57 U1.40
  Bottom Layer w10: 627.58,1820 v1(1580,1820)
ADAC2: SB4.1 U1.41 | length 1454.9
  Top Layer w10: SB4.1 428.89,1817.36 428.89,1801.11 460,1770 600,1770 v1(610,1780) ; v1(1530,1780) 1530,1710 1665.75,1574.25 U1.41
  Bottom Layer w10: v1(610,1780) v1(1530,1780)
AGPIO1: CN6.10 U1.123 | length 744.3
  Top Layer w10: v1(1330,760) 1324.76,760 1320,755.24 1331.1,744.14 U1.123
  Bottom Layer w10: CN6.10 1320,750 v1(1330,760)
AGPIO2: CN6.8 U1.118 | length 808.1
  Top Layer w10: v1(1210,760) 1232.68,737.32 U1.118
  Bottom Layer w10: CN6.8 1120,350 1250,480 1250,650 1210,690 v1(1210,760)
AGPIO3: CN6.5 U1.91 | length 1153.7
  Top Layer w10: v1(900,1110) 905.41,1110 915.25,1100.16 U1.91
  Bottom Layer w10: CN6.5 820,470 790,500 790,640 836,686 836,742.37 840,746.37 840,1030 900,1090 v1(900,1110)
AGPIO4: CN6.3 U1.92 | length 1249.8
  Top Layer w10: v1@850,1075.39 v1(850,1080) ; 865.86,1080.47 U1.92
  Bottom Layer w10: CN6.3 620,310 590,340 590,850 710,970 710,990 800,1080 v1(850,1080)
AMISO: CN6.14 U1.42 | length 1475.5
  Top Layer w10: U1.42 1646.06,1473.94 v1(1660,1460)
  Bottom Layer w10: v1(1660,1460) 1640,1440 1640,750 1720,670 CN6.14
AMOSI: CN6.13 U1.43 | length 1447.7
  Top Layer w10: v1(1610,1460) 1624.37,1460 1626.38,1462.01 U1.43
  Bottom Layer w10: v1(1610,1460) 1610,730 1620,720 CN6.13
ANSS: CN6.12 U1.125 | length 960.6
  Top Layer w10: U1.125 1370.47,780.47 1400,810 v1(1520,810)
  Bottom Layer w10: CN6.12 v1(1520,810)
ASCK: CN6.15 U1.126 | length 1098.7
  Top Layer w10: U1.126 1390.16,740.16 1430,780 v1(1690,780)
  Bottom Layer w10: v1(1690,780) 1690,750 1790,650 1790,130 CN6.15
ASCL: CN6.19 U1.11 | length 1348.5
  Top Layer w10: v1(1730,980) 1747.64,962.36 U1.11
  Bottom Layer w10: v1(1730,980) 1860,850 1860,210 1870,200 2160,200 2220,140 CN6.19
ASDA: CN6.18 U1.10 | length 1202.8
  Top Layer w10: v1(1730,920) 1752.68,942.68 U1.10
  Bottom Layer w10: v1(1730,920) 1820,830 1820,210 1870,160 2080.86,160 2110.43,130.42 2110.43,109.57 CN6.18
AUSART2_RX: CN6.1 U1.37 | length 2692.5
  Top Layer w10: U1.37 1744.49,1624.14 1760,1639.65 v1(1760,1640)
  Bottom Layer w10: CN6.1 420,520 520,620 520,850 650,980 650,1320 990,1660 1740,1660 v1(1760,1640)
AUSART2_TX: CN6.2 U1.36 | length 2455.9
  Top Layer w10: v1(1520,1420) 1720,1420 1754.49,1454.49 U1.36
  Bottom Layer w10: CN6.2 520,560 560,600 560,850 680,970 680,1250 870,1440 1500,1440 v1(1520,1420)
C12V: CN1.1 CN2.1 JP6.1 | length 1255.4
  Top Layer w50: CN2.1 CN2.1@2580,1250
  Bottom Layer w50: JP6.1@2360,1630 2360,1560 2570,1350 CN2.1 2680,1150 2680,700 CN1.1 CN1.1@2586.34,573.66
CANH: CN1.2 CN2.2 D2.1 JP2.1 U4.7 | length 1264.9
  Top Layer w30: U4.7@2150,360 2197.2,360 D2.1 2231.67,325.65 2231.67,361.67 2250,380 2360,380 2380,400 JP2.1 2480,400 2513.95,433.95 2563.95,433.95 CN1.2
  Bottom Layer w30: CN1.2 2559.92,450.08 2529.92,450.08 2480,500 2480,1020 CN2.2
CANL: CN1.3 CN2.3 D2.2 R9.2 U4.6 | length 1508.3
  Top Layer w30: U4.6 2184.74,310 2188.61,306.12 2188.61,303.56 2202.09,290.09 2204.65,290.09 2217.83,276.91 2229.11,276.91 D2.2 2231.61,258.39 2373.16,116.84 2382.61,116.84 R9.2 2397.39,116.84 2436.84,116.84 2480,160 2480,240 2519.92,279.92 2559.92,279.92 CN1.3 2662.43,290 2690,317.57 2690,900 2631.05,958.95 2571.05,958.95 CN2.3
CANRX: TP4.1 U1.73 | length 46.2
  Top Layer w10: TP4.1 981.67,1498.33 U1.73
CANTX: TP5.1 U1.74 | length 128
  Top Layer w10: TP5.1 910,1450 925.2,1434.8 U1.74
DIP0: SB9.1 U1.81 | length 74.5
  Top Layer w10: SB9.1 913.75,1308.01 924.75,1297.01 U1.81
DIP1: SB10.1 U1.82 | length 105
  Top Layer w10: SB10.1 913.75,1264 924.75,1275 928.75,1275 930.75,1277 935.13,1277 935.43,1277.29 U1.82@981.64,1277.29 ; U1.82@954.12,1277.32 U1.82
DIP2: SB11.1 U1.85 | length 77.8
  Top Layer w10: SB11.1@913.75,1200 913.75,1204 924.75,1215 928.75,1215 932.02,1218.27 U1.85
DRX: R27.1 U1.76 | length 1385.1
  Top Layer w10: R27.1 735.3,470 830,470 850,490 v1(890,490) ; U1.76 1034.57,1395.43 v1(1060,1370)
  Bottom Layer w10: v1(890,490) 890,720 990,820 1064.14,820 1078,833.86 1078,918 1120,960 1120,1120 1020,1220 1020,1330 v1(1060,1370)
DTX: R28.2 U1.101 | length 702
  Top Layer w10: v1(820,560) 820.59,559.41 R28.2 ; v1(870,1010) 870,950 916.66,903.34 U1.101@981.64,903.34
  Bottom Layer w10: v1(820,560) 820,620 854,654 854,734.91 860,740.91 860,980 870,990 v1(870,1010)
E5V: C5.1 C19.2 C23.1 C25.1 CN5.5 R34.2 U4.3 U5.1 U5.2 U6.2 U6.4 | length 3786.6
  Top Layer w15: U5.2 1952.8,1642.8 1984.49,1674.49 C19.2@1987.81,1674.49 ; C19.2 1998.03,1684.7 C19.2@1987.81,1674.49 ; C23.1 2035.28,1454.72 1978.39,1511.61 U5.1 1978.39,1663.09 1987.81,1672.52 C19.2@1987.81,1674.49
  Top Layer w20: C5.1 1834.7,284.7 1858.93,308.93 1908.93,308.93 U4.3 2010,310 v1(2020,320) ; v1(2120,1370) C23.1@2120,1433.11 ; R34.2 2157.27,1877.44 2157.27,1842.73 v1(2170,1830) ; U6.2 2280,1485 2300,1505 2310,1505 2322.55,1517.55 2322.55,1522.46 2335.09,1535 2340,1535 C25.1
  Top Layer w50: U6.4 v1(2280,1310) ; v1(2280,1370) U6.2
  Bottom Layer w20: v1(2120,1370) 2250,1370 2280,1340
  Bottom Layer w30: v1(2020,320) 2050,320 2280,550 v1(2280,1310)
  Bottom Layer w50: CN5.5 1420,1940 1480,1880 2140,1880 2170,1850 v1(2170,1830) 2170,1480 v1(2280,1370) 2280,1340 v1(2280,1310)
EECLK: U1.136 U2.6 | length 251.7
  Top Layer w10: U2.6 1500,540 1587.01,627.01 U1.136
EECS1: U1.135 U2.3 | length 654.4
  Top Layer w10: v1(1470,170) 1497.14,197.14 1497.14,247.14 U2.3 ; v1(1470,550) 1567.32,647.32 U1.135
  Bottom Layer w10: v1(1470,170) v1(1470,550)
EESDA: C9.2 R12.2 U1.137 U2.5 | length 383.3
  Top Layer w10: U1.137 1606.69,606.69 1550,550 U2.5 1550,461.25 1561.25,450 1624.7,450 C9.2@1624.7,400
FCAN_RX: SB6.2 U4.4 | length 231
  Top Layer w20: SB6.2 1719.29,250 1729.29,240 1859.07,240 1872.51,253.44 1872.51,257.42 1875.1,260 U4.4
FCAN_STBY: R8.1 U1.141 U4.8 | length 612.5
  Top Layer w10: U1.141 1685.43,666.92 1687.15,665.2 1687.15,656.62 1706.8,636.96 1706.8,622.75 1715.38,622.75 1723,615.13 1723,612 1731.77,612 1773.77,570 1790,570 R8.1@1810,550
  Top Layer w20: R8.1 1822.42,542.28 1822.42,507.58 1870,460 2045.98,460 2093.19,412.8 2095.26,412.8 2098.05,410 U4.8
FCAN_TX: SB5.2 U4.1 | length 252.1
  Top Layer w15: SB5.2 1693.75,331.9 1716.66,354.81 1719.43,354.81 1728.51,363.89 1728.51,366.66 1752.86,391.01 1754.76,391.01 1773.75,410 U4.1
FCANRX: SB6.1 U1.114 | length 829.5
  Top Layer w10: 1150,580 1153.94,583.94 U1.114
  Top Layer w15: 1150,580 1150,417.47 1240.47,327 1563,327 1626.25,263.75 SB6.1
FCANTX: SB5.1 U1.115 | length 746.1
  Top Layer w10: U1.115 1173.62,586.38 1179.5,580.5
  Top Layer w15: 1179.5,580.5 1179.5,440.5 1260,360 1570,360 1600,330 SB5.1
GND: B1.1 C1.2 C2.2 C3.2 C4.2 C5.2 C6.2 C8.1 C9.1 C10.2 C11.1 C12.1 C13.2 C14.2 C15.2 C16.2 C18.1 C19.1 C20.2 C21.2 C22.2 C23.2 C24.2 C25.2 C26.1 C27.1 C28.1 C29.1 CN1.4 CN2.4 CN3.5 CN4.5 CN4.7 CN4.11 CN5.6 CN5.7 CN6.16 CN9.2 D1.2 D1.5 D2.3 R2.2 R5.2 R7.1 R8.2 R10.1 R20.1 R31.1 U1.16 U1.31 U1.38 U1.51 U1.61 U1.83 U1.94 U1.107 U1.120 U1.130 U2.4 U2.7 U3.1 U4.2 U5.7 U5.8 U6.1 X1.2 Z1.1 | length 5292.7
  Top Layer w10: C3.2@430,1380 C3.2@440,1380 ; D1.5 D1.2 740,1005.41 750,995.41 v1(750,990) v1@745.41,990 ; v1(800,700) 800,690 R20.1 ; C27.1 914.19,1041.1 U1.94 1015.02,1041.1 1023.91,1050 v1(1070,1050) ; U1.107 1045.2,785.2 v1(1050,790) ; U1.83 1047.64,1257.64 1060,1270 v1(1060,1280) ; C26.1 1221.97,1665.3 1234.69,1652.58 1234.69,1650.61 1270,1615.3 v1(1270,1590) 1272.05,1587.95 U1.61 ; v1(1270,760) 1272.05,757.95 U1.120 ; v1(1360,630) C28.1 ; v1(1460,1590) 1460,1584.81 1468.9,1575.91 U1.51 ; U1.130 1468.9,748.9 v1(1470,750) ; B1.1@1650,1733.53 B1.1 1650,1710 1724.8,1635.2 U1.38 ; v1(1700,1340) 1710,1340 1726.06,1356.06 U1.31 ; v1(1740,1060) 1740.79,1060.79 U1.16 ; v1(1960,1110) 1960,1066.77 X1.2 1960,1059.84 1960,1030.98 1930.78,1001.76 1930.78,929.81 1967.94,892.65 1992.65,892.65 v1(2000,900) ; C15.2 v1(1970,850) ; C16.2 v1(2320,440)
  Top Layer w15: CN3.5 265.53,1057.46 312.54,1057.46 v1(350,1020) ; v1(420,1450) C3.2 C3.2@430,1380 ; v1(880,1630) C1.2 ; v1(1060,260) C2.2 ; C10.2 1254.92,439.78 1254.92,435.08 v1(1280,410) ; CN5.6 1328.61,1966.19 1328.61,1946.09 1392.52,1882.19 1394.49,1882.19 1404.7,1871.97 C29.1 ; v1(1430,410) 1447.97,427.97 1447.97,473.96 U2.7 ; U2.4 1552.03,247.97 1552.03,197.97 v1(1580,170) ; C9.1 1695.3,391.97 1705.51,402.19 1712.19,402.19 v1(1760,450) ; v1(1780,710) 1784.06,710 1791.87,702.19 1804.49,702.19 1814.7,691.97 C8.1@1814.7,690 ; R8.2 1890,545.3 v1(1890,500) ; U5.7 1952.8,1394.7 C22.2 ; C22.2@1978.39,1370.89 U5.8 ; C21.2@1995.28,1300 2000,1295.28 C14.2
  Top Layer w20: v1(64.7,1480) R7.1 R7.1@105.3,1480.59 ; v1(190,740) 190.59,740.59 R2.2 190.59,869.41 C4.2 ; v1(350,1020) 351.91,1018.09 351.91,1012.79 410.31,954.39 410.31,952.42 418.03,944.7 R5.2 ; v1(1590,520) 1635.3,520 R10.1 ; B1.1@1650,1733.53 1664.7,1748.23 C12.1 ; C5.2 1784.7,360 U4.2 1960,360 1990,390 v1(2005,390) ; C18.1 1907.72,762.42 1921.87,762.42 1954.41,794.96 1954.41,795.55 1969.41,810.55 C15.2 ; R31.1 C19.1 2000.55,1755.85 2000.55,1780 ; C22.2@1978.39,1370.89 C22.2 ; C21.2@1995.28,1300 1995.28,1352.22 C22.2 ; C20.2 2000.55,1780 ; v1(2020,1370) C22.2 ; v1(2030,1780) 2000.55,1780 ; C23.2 2108.28,1553.55 2108.28,1592.92 2115.3,1599.94 v1(2115.3,1602.65) 2115.3,1620 C13.2 ; C6.2 2186.59,188.7 2221.3,188.7 2310,100 v1(2310,70) ; D2.3 2308.39,261.61 v1(2310,260) ; U6.1 2370.55,1485 2395,1509.45 2395,1535 C25.2
  Top Layer w40: v1(2270,1560) C24.2 ; U3.1@2330,1125.71 2360.71,1125.71 2390,1155 2390,1435.55 2370.55,1455 U6.1 ; Z1.1@2561.42,1972.83 Z1.1 v1(2670,1980)
  Top Layer w50: v1(2330,950) U3.1 U3.1@2330,1125.71 ; U6.1 2440,1470 2570,1600 CN9.2
LED1: R25.1 U1.67 | length 1037
  Top Layer w10: R25.1 780,1700 810,1730 1110,1730 1153.94,1686.06 U1.67
LED2: R29.1 U1.68 | length 1001.3
  Top Layer w10: R29.1 780,1630 840,1690 1110,1690 1134.25,1665.75 U1.68
NetC1_1: C1.1 U1.71 | length 108
  Top Layer w10: C1.1 1075.2,1614.8 U1.71
NetC2_1: C2.1 U1.106 | length 658.2
  Top Layer w10: U1.106 1025.28,804.88 1038.4,818 1082,818 1110,790 v1(1110,780) ; v1(990,430) C2.1
  Bottom Layer w10: v1(990,430) 990,460 950,500 950,620 v1(1110,780)
NetC3_1: C3.1 D1.6 R4.1 SB2.1 | length 906.5
  Top Layer w10: R4.1 105.3,1399.41 v1(105.3,1330)
  Top Layer w20: C3.1 580,1340 v1(600,1340) 683.75,1256.25 SB2.1 683.75,1178.49 695.47,1166.77 700.79,1166.77 702.6,1164.96 D1.6
  Bottom Layer w10: v1(105.3,1330) 125.3,1350 590,1350 v1(600,1340)
NetC4_1: C4.1 CN3.Shell R2.1 | length 778.9
  Top Layer w25: CN3.Shell@114.57,957.44 119.41,952.6 C4.1 119.41,790.59 R2.1
  Bottom Layer w25: CN3.Shell@264.17,963.35 258.27,957.44 114.57,957.44 114.57,1262.56 258.27,1262.56 CN3.Shell@264.17,1256.65
NetC13_1: C13.1 JP1.2 L1.2 U1.33 | length 588.8
  Top Layer w10: U1.33 1864.14,1395.43 1876.66,1407.95 v1(1876.66,1520) 1876.66,1553.34 1850.59,1579.41 1850.59,1580 1830.59,1600 L1.2 ; v1(2020,1610) 2023.83,1613.83 2038.53,1613.83 2040.02,1615.31 2041.99,1615.31 2058.83,1632.15 2058.83,1658.83 JP1.2
  Bottom Layer w10: v1(1876.66,1520) 1930,1520 v1(2020,1610)
NetC15_1: C15.1 C16.1 JP5.2 U3.2 U3.4 | length 1258
  Top Layer w20: U3.4 2232.5,660.02 C16.1
  Top Layer w30: JP5.2 2197.48,630 U3.4 2172.52,720 C15.1
  Top Layer w40: U3.4 U3.2 U3.2@2230,1139.71
NetC20_1: C20.1 U5.4 | length 244.4
  Top Layer w15: U5.4 1901.61,1629.05 1901.27,1629.4 1900.6,1629.4 1880,1650 1880,1790 1891.91,1801.91 1892.5,1801.91 1910,1819.41 C20.1
NetCN3_1: CN3.1 SB2.2 | length 376.4
  Top Layer w15: CN3.1 341.18,1161.18 400,1220 SB2.2
NetCN3_4: CN3.4 R5.1 | length 185.6
  Top Layer w10: CN3.4 350.89,1084.41 405.31,1029.98 405.31,1028.01 418.03,1015.3 R5.1
NetCN4_4: CN4.4 R19.1 | length 74.7
  Top Layer w10: CN4.4 R19.1
NetCN4_6: CN4.6 R21.1 | length 340.3
  Top Layer w10: CN4.6 700,720 770,650 924.7,650 964.7,610 R21.1
NetCN4_8: CN4.8 R22.1 | length 622.7
  Top Layer w10: CN4.8 720,670 760,630 850,630 910,570 v1(1010,570) ; v1(1210,600) 1234.7,600 R22.1@1244.7,610
  Bottom Layer w10: v1(1010,570) 1170,570 1200,600 v1(1210,600)
NetCN4_10: CN4.10 R24.1 | length 332
  Top Layer w10: CN4.10 690,610 820,610 900,530 R24.1
NetCN4_12: CN4.12 D3.2 | length 267.3
  Top Layer w10: v1(742.83,430) 745.66,430 752.83,437.17 829.92,437.17 D3.2
  Bottom Layer w10: CN4.12 720,530 720,470 742.83,447.17 v1(742.83,430) v1@750,430
NetCN4_13: CN4.13 R27.2 | length 92.2
  Top Layer w10: R27.2 624.7,508.89 630,514.18 CN4.13
NetCN4_14: CN4.14 R28.1 | length 70
  Top Layer w10: CN4.14 R28.1
NetCN5_1: CN5.1 R34.1 | length 476.6
  Top Layer w20: CN5.1 2185.2,1974.8 2225.3,1934.7 R34.1
NetCN5_14: CN5.14 SB3.2 | length 81.1
  Top Layer w10: SB3.2 CN5.14
NetCN5_15: CN5.15 SB4.2 | length 81.1
  Top Layer w10: SB4.2 CN5.15
NetCN6_17: CN6.17 SB8.1 | length 95.4
  Top Layer w10: CN6.17 CN6.17@2020,102.86
  Top Layer w15: SB8.1 2013.75,106.25 CN6.17
NetCN9_1: CN9.1 JP6.3 | length 222.4
  Top Layer w50: JP6.3@2360,1830 2440,1830 2470,1800 CN9.1
NetJP2_2: JP2.2 R9.1 | length 100
  Top Layer w20: R9.1 JP2.2
NetLD1_2: LD1.2 R25.2 | length 72
  Top Layer w10: LD1.2 R25.2
NetLD2_2: LD2.2 R29.2 | length 73.4
  Top Layer w10: LD2.2 R29.2
NetR1_1: R1.1 X1.1 | length 206.7
  Top Layer w15: X1.1 2010,1023.23 2010,1134.7 2002.19,1142.52 2002.19,1144.49 1991.97,1154.7 R1.1
NetR3_2: R3.2 T1.2 | length 187.1
  Top Layer w15: T1.2 272.05,1310 R3.2
NetR4_2: R4.2 R6.1 R7.2 T1.1 | length 220.3
  Top Layer w10: R7.2 R4.2 219.21,1400 223.11,1403.9 225.94,1403.9 T1.1 240.63,1463.96 254.7,1478.03 R6.1
NetR10_2: R10.2 SB7.1 U1.138 | length 152.7
  Top Layer w10: U1.138 1626.38,643.62 1640,630 R10.2 1641.55,593.75 SB7.1
NetR11_2: R11.2 U1.143 | length 146.4
  Top Layer w10: U1.143 1724.8,638.79 1733.59,630 R11.2
NetR13_2: R13.2 SB9.2 | length 50.6
  Top Layer w10: R13.2@844.7,1360 846.25,1358.45 SB9.2
NetR14_2: R14.2 SB10.2 | length 58.2
  Top Layer w10: R14.2 794.7,1260 SB10.2
NetR15_2: R15.2 SB11.2 | length 50.6
  Top Layer w10: R15.2 846.25,1161.55 SB11.2
NetR17_1: R17.1 X1.3 | length 98.1
  Top Layer w15: X1.3 1896.54,1135.7 1897.81,1136.98 1897.81,1144.49 1908.03,1154.7 R17.1
NetR31_2: R31.2 U5.3 | length 89.9
  Top Layer w15: R31.2 1927.2,1677.5 U5.3
NetTP1_1: TP1.1 U1.24 | length 546
  Top Layer w10: v1(1750,1190) 1778.27,1218.27 U1.24
  Bottom Layer w10: v1(1750,1190) 2030,1470 TP1.1
NRST: B1.2 C12.2 CN5.3 D3.1 U1.25 | length 2590.9
  Top Layer w10: v1(880,380) 920,420 920,433.1 913.1,440 D3.1 ; v1(1060,1110) 1180,1230 v1(1670,1230) 1677.95,1237.95 U1.25
  Top Layer w20: CN5.3 1625.02,1969.78 1625.02,1934.98 1727.58,1832.42 1727.58,1817.72 C12.2 1735.3,1808.03 1750,1793.33 B1.2
  Bottom Layer w10: v1(880,380) 860,400 860,543.7 872,555.7 872,727.46 880,735.46 880,930 v1(1060,1110) ; v1(1670,1230) 1670,1420 1700,1450 1700,1510 1790,1600 1790,1680 B1.2
PB14: CN6.7 U1.75 | length 1589.9
  Top Layer w10: U1.75 1074.88,1415.12 1090,1400 v1(1170,1400)
  Bottom Layer w10: CN6.7 1020,500 980,540 980,600 1170,790 v1(1170,1400)
PC2_C: CN5.10 U1.28 | length 1379
  Top Layer w10: CN5.10 994.8,1900 1280,1900 v1(1560,1620) ; v1@1567.01,1297.01 v1(1563.5,1293.5) 1567.01,1290 1768.97,1290 1775.98,1297.01 U1.28
  Bottom Layer w10: v1(1560,1620) 1560,1297.01 v1(1563.5,1293.5)
PC9: CN6.4 U1.99 | length 1132.1
  Top Layer w10: v1(755,720) 765,730 860,730 v1(910,780) ; U1.99 1015.02,942.68 1050,907.69 v1(1050,860)
  Bottom Layer w10: CN6.4 720,180 772,232 772,462.29 755,479.29 v1(755,720) ; v1(910,780) 990,860 v1(1050,860)
PD15: CN6.6 U1.86 | length 1374.7
  Top Layer w10: U1.86 1048.58,1198.58 1070,1220 v1(1110,1220)
  Bottom Layer w10: CN6.6 920,630 1030,740 1030.4,740 1051.6,761.2 1060.8,761.2 1082,782.4 1082,791.6 1137.8,847.39 1137.8,951.5 1150,963.7 1150,1180 v1(1110,1220)
PE6: CN6.11 U1.5 | length 1179
  Top Layer w10: v1(1400,850) 1405.75,844.25 U1.5
  Bottom Layer w10: v1(1400,850) 1400,350 1420,330 CN6.11
PF11: CN5.11 U1.49 | length 910.3
  Top Layer w10: CN5.11 924.8,1870 1230,1870 1508.27,1591.73 U1.49
PF13: CN5.12 U1.53 | length 937.1
  Top Layer w10: CN5.12 854.8,1840 1190,1840 1430,1600 1429.56,1599.56 U1.53@1429.56,1528.36
PF14: CN5.13 U1.54 | length 999.3
  Top Layer w10: CN5.13 794.8,1800 1180,1800 1409.84,1570.16 U1.54
PH0: R17.2 U1.23 | length 102.7
  Top Layer w10: U1.23 1868.58,1198.58 1883.34,1213.34 1898.04,1213.34 R17.2
T_TDI: R24.2 R26.2 U1.110 | length 235.7
  Top Layer w10: R24.2@1042.56,535.3 1035.3,528.03 1035.3,531.97 1040.59,537.26 1048.01,544.69 R24.2@1049.98,544.69 ; R24.2 1077.8,562.5 1077.8,573.09 1095.31,590.61 1105,600.3 R26.2@1109.02,604.31 ; U1.110 1075.2,658.13 1110,623.33 R26.2
T_TDO: R22.2 R23.2 U1.133 | length 362.8
  Top Layer w10: R23.2 R22.2 1325.3,590 1484.14,590 1527.95,633.81 U1.133
TCK-SWCLK: R20.2 R21.2 U1.109 | length 299
  Top Layer w10: R20.2 1040,690 R21.2@1040,616.67 ; R21.2@1035.3,610 1035.3,611.97 R21.2@1040,616.67 ; U1.109 1055.51,630.54 1049.65,624.69 1048.01,624.69 R21.2@1040,616.67
TMS-SWDIO: R18.2 R19.2 U1.105 | length 208.3
  Top Layer w10: R19.2 825.3,820 829.86,824.57 U1.105
USBDM: CN3.2 D1.1 U1.103 | length 913.8
  Top Layer w10: 710,960 800,960 896.06,863.94 U1.103
  Top Layer w15: CN3.2 534.41,1135.59 620,1050 ; D1.1 622.76,1052.76 620,1050 ; 710,960 620,1050
USBDP: CN3.3 D1.3 R3.1 U1.104 | length 1304.1
  Top Layer w10: D1.3 777.4,1035.04 789.94,1022.5 789.94,990.06 v1(790,990) ; v1(790,900) 790,930 790,940 885.75,844.25 U1.104
  Top Layer w15: CN3.3 460,1110 ; v1(460,1080) 460,1110 ; R3.1 485.3,1264.7 v1(490,1260) ; 790,930 680,930 500,1110 460,1110
  Bottom Layer w10: v1(790,900) v1(790,990)
  Bottom Layer w15: v1(460,1080) 490,1110 v1(490,1260)
USBEN: R6.2 U1.102 | length 1049
  Top Layer w10: R6.2 335.3,1490 530,1490 720,1300 720,1260 790.23,1189.77 794.6,1189.77 810,1174.37 810,1019.6 818,1011.6 818,972 906.38,883.62 U1.102
VIN: C14.1 C24.1 CN5.8 JP6.2 U3.3 U6.3 Z1.2 | length 2587.6
  Top Layer w20: C14.1 2124.72,1204.72
  Top Layer w50: CN5.8 1120,2010 1180,2070 2301.42,2070 Z1.2 2371.14,1959.72 2359.72,1959.72 2290,1890 2290,1760 2302.66,1747.34 2320,1730 ; 2124.72,1204.72 2124.72,1274.72 2189.45,1339.45 U6.3 2189.45,1679.45 2225.28,1715.28 C24.1 2270.59,1715.28 2285.31,1730 2320,1730 ; U3.3 2130,1210 ; JP6.2 2320,1730
VREF+: C21.1 C22.1 JP1.1 SB8.2 U1.32 U5.5 U5.6 | length 2349.3
  Top Layer w10: v1(1730,1390) 1731.61,1390 1745.86,1375.75 U1.32 C22.1@1916.75,1375.75 ; U5.5 1901.61,1390.89 C22.1@1916.75,1375.75 ; C22.1 C22.1@1916.75,1375.75 ; SB8.2 1956.73,200.48 1956.73,216.73 v1(1980,240)
  Top Layer w15: C21.1@1904.72,1300 1922.5,1317.78 C22.1 1927.2,1374.7 U5.6
  Bottom Layer w10: v1(1980,240) 1980,300 1920,360 1920,850 1860,910 1860,1040 1720,1180 1720,1220 1730,1230 v1(1730,1390) 1730,1490 1900,1660 1960,1660 JP1.1
pads on no net: CN3.MH1 CN3.MH2 CN4.1 CN4.2 CN4.9 CN5.9 CN6.9 D1.4 M1.1 M3.1 U1.1 U1.2 U1.3 U1.4 U1.7 U1.8 U1.9 U1.12 U1.13 U1.14 U1.15 U1.18 U1.19 U1.20 U1.21 U1.22 U1.26 U1.27 U1.29 U1.34 U1.35 U1.44 U1.45 U1.46 U1.47 U1.48 U1.50 U1.55 U1.56 U1.57 U1.58 U1.59 U1.60 U1.63 U1.64 U1.65 U1.66 U1.69 U1.70 U1.77 U1.78 U1.79 U1.80 U1.87 U1.88 U1.89 U1.90 U1.93 U1.96 U1.97 U1.98 U1.100 U1.111 U1.112 U1.113 U1.116 U1.117 U1.119 U1.122 U1.124 U1.127 U1.128 U1.129 U1.132 U1.134 U1.139 U1.140 U1.142 U2.1 U2.2
copper on no net: | length 20760
  Top Layer w10: 0,0 0,2140 2780,2140 2780,0 0,0 ; 230,650 420,650 420,730 230,730 230,650
  Bottom Layer w10: 0,0 0,1560 0,2140 2780,2140 2780,0 0,0 ; 230,650 230,730 420,730 420,650 230,650

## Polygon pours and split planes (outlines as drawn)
GND on Top Layer "Top Layer-GND" (solid, pour order 2): 880,1680 890,1670 1870,1670 1870,1390 2020,1390 2020,900 2010,890 1930,890 1920,880 1920,600 880,600
GND on GND (split plane): 2759.9,2119.9 2759.9,20.1 20.1,20.1 20.1,2119.9
3V3 on 3V3 (split plane): 2759.9,2119.9 2759.9,20.1 20.1,20.1 20.1,2119.9

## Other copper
Top Layer:
  text "TOP" at 250,660 h60
Bottom Layer:
  text "BOT" at 410,660 h60

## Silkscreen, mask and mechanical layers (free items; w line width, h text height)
Top Overlay:
  lines w10: 470,60 470,140 470,150 ; 370,50 370,150 2270,150 2270,50 370,50
  text "CAN FD" at 30,560 h55
  text "2020-10-01" at 40,480 h45
Mechanical 1:
  lines w15: -10,0 2789.71,0 2789.71,2150 -10,2150 -10,0

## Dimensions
-280,2150 to -240,0 on Mechanical 1
-10,-130 to 2790,-180 on Mechanical 1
